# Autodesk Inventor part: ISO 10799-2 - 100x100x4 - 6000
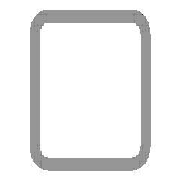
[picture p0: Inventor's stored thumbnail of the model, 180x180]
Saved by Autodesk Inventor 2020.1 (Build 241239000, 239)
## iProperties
Created: 2019-10
Part Number: ISO 10799-2 - 100x100x4 - 6000
Material: Stainless Steel
Description: Structural steels - Cold-formed, welded, structural hollow sections
Document SubType Name: Modeling
Standard: ISO
Designer: Synergysoft Dell02
Standard Revision: First edition 2011-09-15
Standards Organization: ISO
Language: en-US
Size Designation: 100x100x4
Categories: <MemberInstance><Categories><Category DisplayName="Structural Shapes" InternalName="089c4875-fa83-4c05-b084-43b9cc11f5ed" Mnemonic="GRDR"><CategoryParameter Dis
Stock Number: 100x100x4
Density: 8 g/cm^3
Appearance: Semi-Polished
_CCFamilyMember: 43
_CCFamilyDisplayName: ISO 10799-2 (Square) - Structural steels - Cold-formed, welded, structural hollow sections
_FrameMemberDoc: Frame Member File
_Version: 15.0.0
_GetPNFromCC: 1
G_L: 6000.000 mm
G_W: 100.000 mm
G_H: 100.000 mm
IsCustomPart: 1
Author: Synergysoft Dell02
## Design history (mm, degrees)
node "Start Plane"
node "End Plane"
sketch "Sketch"
  geometry: L1 (-50, -42)-(-50, 42); L2 (-42, 50)-(42, 50); L3 (50, 42)-(50, -42); L4 (42, -50)-(-42, -50); L5 (-42, 46)-(42, 46); L6 (46, 42)-(46, -42); L7 (42, -46)-(-42, -46); L8 (-46, -42)-(-46, 42); L9 (0, 72.32)-(0, -72.32) reference; L10 (-72.32, 0)-(72.32, 0) reference; A1 r 8 centre (-42, -42) between (-50, -42) and (-42, -50); A2 r 8 centre (42, 42) between (50, 42) and (42, 50); A3 r 8 centre (-42, 42) between (-42, 50) and (-50, 42); A4 r 8 centre (42, -42) between (42, -50) and (50, -42); A5 r 4 centre (-42, 42) between (-42, 46) and (-46, 42); A6 r 4 centre (42, 42) between (46, 42) and (42, 46); A7 r 4 centre (42, -42) between (42, -46) and (46, -42); A8 r 4 centre (-42, -42) between (-46, -42) and (-42, -46)
  constraints: 16 end point, 16 point on circle, 8 centre point, 8 tangent, 4 parallel, 3 equal radius, 2 perpendicular, 7 other
  dimensions: "d7" = 8 radius of A1 (= G_IR); "d9" = 100 distance between parallel lines of L1 L3 (= G_W); "d11" = 100 distance between parallel lines of L2 L4 (= G_H); "d12" = 4 distance between parallel lines of L3 L6 (= G_T); "d15" = 50 distance between parallel lines of L9 L3 (= 0.5 x d9); "d16" = 50 distance between parallel lines of L2 L10 (= 0.5 x d11)
extrude "Body" new body sketch "Sketch" stored distance "d3" = 6000 (= G_L); taper "d4" = 0 deg
node "Driven Length"
  sketch "Sketch3"
    geometry: L1 (0, 0)-(10, 0) reference
    constraints: 2 end point, 1 horizontal
  workplane "Work Plane3"
  sketch "Sketch4"
    geometry: L1 (-2, 0)-(12, 0) reference; L2 (-2, 6000)-(12, 6000) reference
    dimensions: "d18" = 6000 distance between parallel lines of L1 L2 (derived)
body "Solid1"
other parameters: "G_W" = 100 [user parameter; used in 1 equation term], "G_H" = 100 [user parameter; used in 1 equation term], "G_T" = 4 [user parameter; used in 1 equation term], "G_IR" = 8 [user parameter; used in 1 equation term], "G_L" = 6000 (= d18) [user parameter; used in 1 equation term], "G_OFFSET_START" = 0 [user parameter; used in 1 equation term], "G_OFFSET_END" = 0 [user parameter; used in 1 equation term], "d13" = 0 (computed from G_OFFSET_START), "d17" = 90 deg, "MAS" = 1.17 [user parameter]
